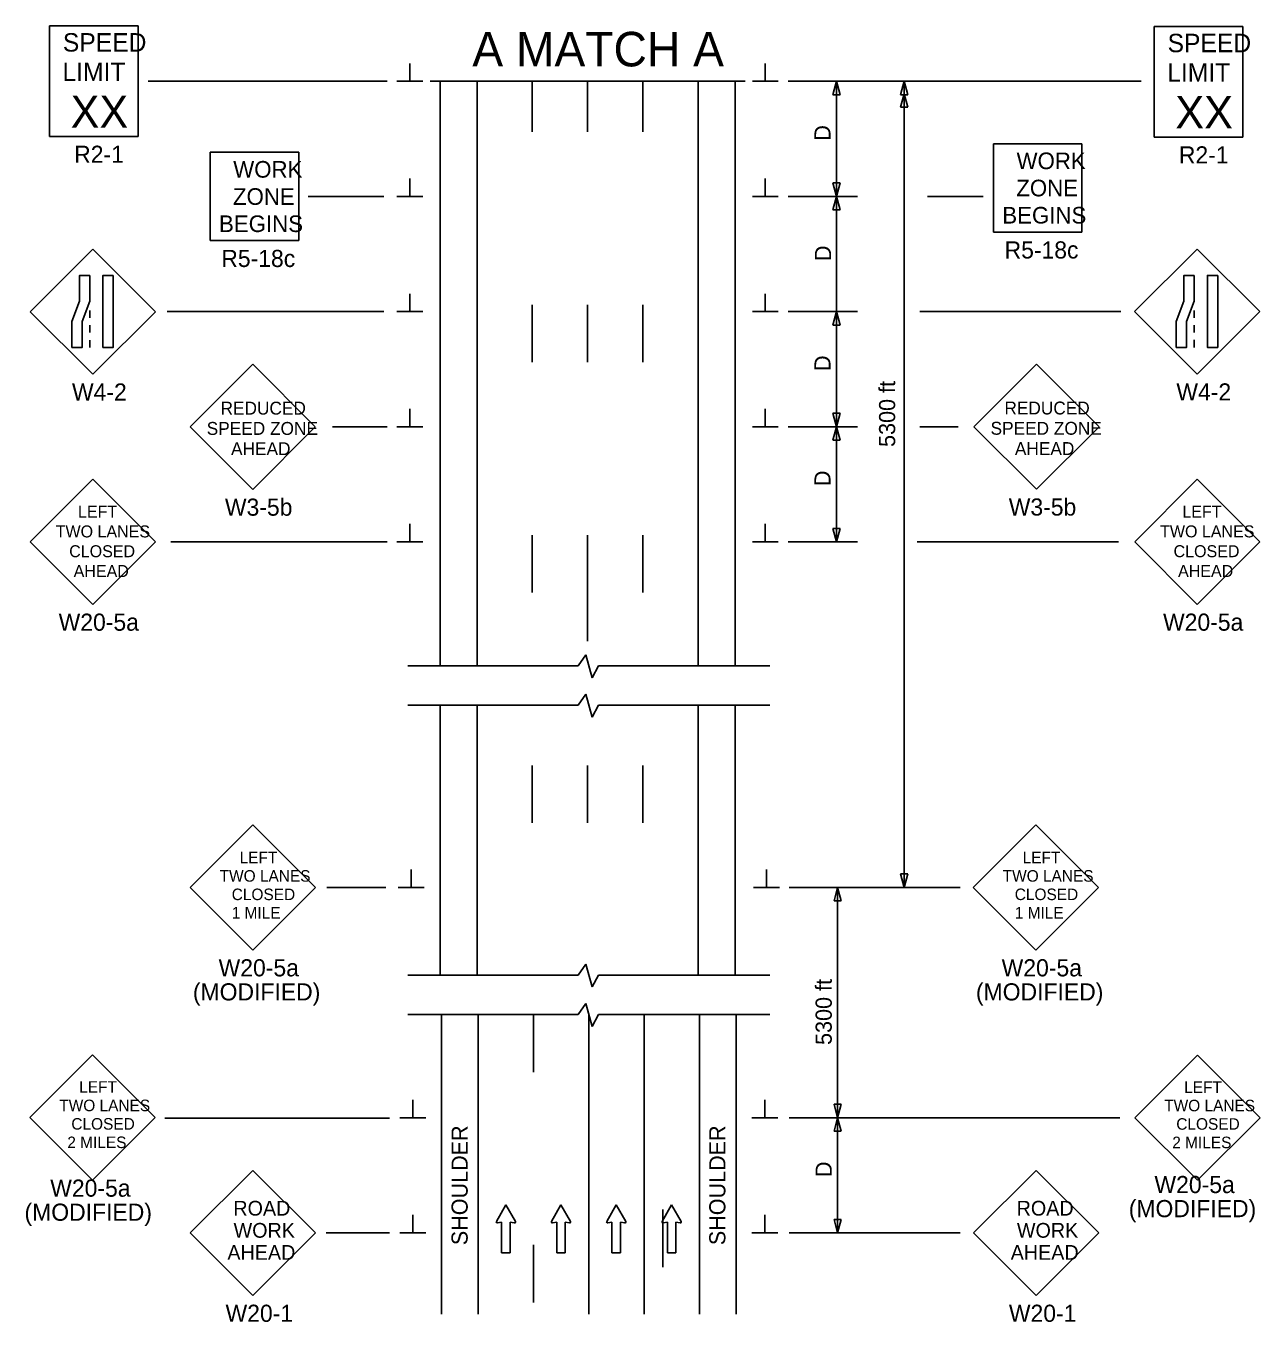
# Model space of a CAD drawing. Extents: x 16486 to 19505, y 5576 to 6998.
# Drawn here: x 17836 to 18371, y 6359 to 6921 of the extents above; entities that cross this region are included whole.
import ezdxf

# ---------------------------------------------------------------- set-up
doc = ezdxf.new("R2010")
doc.units = 0
for name, color, linetype in [('ALI_LEGAL_EX', 7, 'Continuous'), ('MT_SCRATCH_LEVEL_E', 7, 'Continuous'), ('PAVT_EDGE_EX', 7, 'Continuous'), ('TRAFFIC_SIGNS_PR', 7, 'Continuous'), ('TYPICAL_TEXT_DIMEN_PR', 7, 'Continuous')]:
    doc.layers.add(name, color=color, linetype=linetype)

msp = doc.modelspace()

# ---------------------------------------------------------------- linework, layer by layer
at = {"layer": 'ALI_LEGAL_EX'}
for p, q in [((18080.13, 6492.04), (18080.13, 6361.96)), ((18104.13, 6492.04), (18104.13, 6361.96))]:
    msp.add_line(p, q, dxfattribs=at)
for points in [[(18055.61, 6875.22), (18055.61, 6897.24)], [(18079.61, 6875.22), (18079.61, 6897.24)], [(18103.61, 6875.22), (18103.61, 6897.24)], [(18055.61, 6775.22), (18055.61, 6800.22)], [(18079.61, 6775.22), (18079.61, 6800.22)], [(18103.61, 6775.22), (18103.61, 6800.22)], [(18055.61, 6700.22), (18055.61, 6675.22)], [(18079.61, 6700.22), (18079.61, 6675.22)], [(18103.61, 6675.22), (18103.61, 6700.22)], [(18079.61, 6679.08), (18079.61, 6654.08)], [(18055.61, 6600.22), (18055.61, 6575.22)], [(18079.61, 6600.22), (18079.61, 6575.22)], [(18103.61, 6575.22), (18103.61, 6600.22)], [(18056.13, 6492.04), (18056.13, 6467.04)], [(18080.13, 6492.04), (18080.13, 6467.04)], [(18104.13, 6492.04), (18104.13, 6467.04)], [(18112.27, 6407.39), (18112.27, 6382.39)], [(18056.13, 6392.04), (18056.13, 6367.04)], [(18080.13, 6392.04), (18080.13, 6367.04)], [(18104.13, 6392.04), (18104.13, 6367.04)]]:
    msp.add_lwpolyline(points, dxfattribs=at)
at = {"layer": 'MT_SCRATCH_LEVEL_E'}
for p, q in [((18044.13, 6409.47), (18040.02, 6402.23)), ((18048.27, 6402.23), (18044.13, 6409.47)), ((18068.03, 6409.47), (18063.92, 6402.23)), ((18072.18, 6402.23), (18068.03, 6409.47)), ((18092.03, 6409.47), (18087.92, 6402.23)), ((18096.18, 6402.23), (18092.03, 6409.47)), ((18116.08, 6409.47), (18111.97, 6402.23)), ((18120.23, 6402.23), (18116.08, 6409.47)), ((18040.5, 6401.54), (18042.28, 6401.86)), ((18042.28, 6401.86), (18042.28, 6388.6)), ((18046.02, 6388.6), (18046.02, 6401.86)), ((18046.02, 6401.86), (18047.79, 6401.54)), ((18064.4, 6401.54), (18066.18, 6401.86)), ((18066.18, 6401.86), (18066.18, 6388.6)), ((18069.92, 6388.6), (18069.92, 6401.86)), ((18069.92, 6401.86), (18071.7, 6401.54)), ((18088.4, 6401.54), (18090.18, 6401.86)), ((18090.18, 6401.86), (18090.18, 6388.6)), ((18093.92, 6388.6), (18093.92, 6401.86)), ((18093.92, 6401.86), (18095.7, 6401.54)), ((18112.46, 6401.54), (18114.23, 6401.86)), ((18114.23, 6401.86), (18114.23, 6388.6)), ((18117.97, 6388.6), (18117.97, 6401.86)), ((18117.97, 6401.86), (18119.75, 6401.54)), ((18042.28, 6388.6), (18046.02, 6388.6)), ((18066.18, 6388.6), (18069.92, 6388.6)), ((18090.18, 6388.6), (18093.92, 6388.6)), ((18114.23, 6388.6), (18117.97, 6388.6))]:
    msp.add_line(p, q, dxfattribs=at)
for centre, start, end in [((18040.42, 6402), 150.4248, 279.9638), ((18047.86, 6402), 260.0362, 29.7731), ((18064.33, 6402), 150.4248, 279.9638), ((18071.77, 6402), 260.0362, 29.7731), ((18088.33, 6402), 150.4248, 279.9638), ((18095.77, 6402), 260.0362, 29.7731), ((18112.38, 6402), 150.4248, 279.9638), ((18119.82, 6402), 260.0362, 29.7731)]:
    msp.add_arc(centre, 0.463, start, end, dxfattribs=at)
at = {"layer": 'PAVT_EDGE_EX'}
for p, q in [((18015.61, 6897.24), (18015.61, 6643.43)), ((18031.61, 6897.24), (18031.61, 6643.43)), ((18127.61, 6897.24), (18127.61, 6643.43)), ((18143.61, 6897.24), (18143.61, 6643.43)), ((18015.61, 6626.3), (18015.61, 6509.16)), ((18031.61, 6626.3), (18031.61, 6509.16)), ((18127.61, 6626.3), (18127.61, 6509.16)), ((18143.61, 6626.3), (18143.61, 6509.16)), ((18016.13, 6492.02), (18016.13, 6361.96)), ((18032.13, 6492.02), (18032.13, 6361.96)), ((18128.13, 6492.02), (18128.13, 6361.96)), ((18144.13, 6492.02), (18144.13, 6361.96))]:
    msp.add_line(p, q, dxfattribs=at)
at = {"layer": 'TRAFFIC_SIGNS_PR'}
for p, q in [((17846.08, 6921.27), (17884.48, 6921.27)), ((17846.08, 6873.27), (17846.08, 6921.27)), ((17884.48, 6873.27), (17884.48, 6921.27)), ((18325.58, 6921), (18363.98, 6921)), ((18325.58, 6873), (18325.58, 6921)), ((18363.98, 6873), (18363.98, 6921)), ((17846.08, 6873.27), (17884.48, 6873.27)), ((18325.58, 6873), (18363.98, 6873)), ((17915.81, 6828.04), (17915.81, 6866.44)), ((17915.81, 6866.44), (17954.21, 6866.44)), ((17954.21, 6828.04), (17954.21, 6866.44)), ((18255.79, 6831.73), (18255.79, 6870.13)), ((18255.79, 6870.13), (18294.19, 6870.13)), ((18294.19, 6831.73), (18294.19, 6870.13)), ((17915.81, 6828.04), (17954.21, 6828.04)), ((18255.79, 6831.73), (18294.19, 6831.73)), ((17864.85, 6824.36), (17837.7, 6797.2)), ((17892.01, 6797.2), (17864.85, 6824.36)), ((18344.2, 6824.39), (18317.05, 6797.23)), ((18371.35, 6797.23), (18344.2, 6824.39)), ((17837.7, 6797.2), (17864.85, 6770.05)), ((17863.61, 6797.7), (17863.61, 6794.5)), ((17864.85, 6770.05), (17892.01, 6797.2)), ((18317.05, 6797.23), (18344.2, 6770.08)), ((18342.95, 6797.72), (18342.95, 6794.52)), ((18344.2, 6770.08), (18371.35, 6797.23)), ((17863.61, 6791.3), (17863.61, 6788.1)), ((18342.95, 6791.32), (18342.95, 6788.12)), ((17863.61, 6784.9), (17863.61, 6781.7)), ((18342.95, 6784.92), (18342.95, 6781.72)), ((17934.24, 6774.36), (17907.09, 6747.21)), ((17961.39, 6747.21), (17934.24, 6774.36)), ((18274.46, 6774.41), (18247.31, 6747.26)), ((18301.61, 6747.26), (18274.46, 6774.41)), ((17907.09, 6747.21), (17934.24, 6720.05)), ((17934.24, 6720.05), (17961.39, 6747.21)), ((18247.31, 6747.26), (18274.46, 6720.11)), ((18274.46, 6720.11), (18301.61, 6747.26)), ((17864.88, 6724.41), (17837.73, 6697.26)), ((17892.03, 6697.26), (17864.88, 6724.41)), ((18344.23, 6724.43), (18317.07, 6697.28)), ((18371.38, 6697.28), (18344.23, 6724.43)), ((17837.73, 6697.26), (17864.88, 6670.11)), ((17864.88, 6670.11), (17892.03, 6697.26)), ((18317.07, 6697.28), (18344.23, 6670.12)), ((18344.23, 6670.12), (18371.38, 6697.28)), ((17934.32, 6574.42), (17907.13, 6547.24)), ((17961.5, 6547.24), (17934.32, 6574.42)), ((18274.19, 6574.43), (18247.01, 6547.24)), ((18301.38, 6547.24), (18274.19, 6574.43)), ((17907.13, 6547.24), (17934.32, 6520.05)), ((17934.32, 6520.05), (17961.5, 6547.24)), ((18247.01, 6547.24), (18274.19, 6520.05)), ((18274.19, 6520.05), (18301.38, 6547.24)), ((17864.71, 6474.47), (17837.52, 6447.28)), ((17891.89, 6447.28), (17864.71, 6474.47)), ((18344.29, 6474.42), (18317.11, 6447.24)), ((18371.48, 6447.24), (18344.29, 6474.42)), ((17837.52, 6447.28), (17864.71, 6420.1)), ((17864.71, 6420.1), (17891.89, 6447.28)), ((18317.11, 6447.24), (18344.29, 6420.05)), ((18344.29, 6420.05), (18371.48, 6447.24)), ((17934.3, 6424.35), (17907.15, 6397.2)), ((17961.46, 6397.2), (17934.3, 6424.35)), ((18274.29, 6424.35), (18247.14, 6397.2)), ((18301.44, 6397.2), (18274.29, 6424.35)), ((17907.15, 6397.2), (17934.3, 6370.05)), ((17934.3, 6370.05), (17961.46, 6397.2)), ((18247.14, 6397.2), (18274.29, 6370.05)), ((18274.29, 6370.05), (18301.44, 6397.2))]:
    msp.add_line(p, q, dxfattribs=at)
for points in [[(17863.61, 6812.94), (17863.61, 6801.76), (17860.26, 6792.88), (17860.26, 6781.7), (17855.77, 6781.7), (17855.77, 6792.88), (17859.11, 6801.76), (17859.11, 6812.94)], [(17873.74, 6812.94), (17873.74, 6781.7), (17869.25, 6781.7), (17869.25, 6812.94)], [(18342.95, 6812.97), (18342.95, 6801.79), (18339.61, 6792.91), (18339.61, 6781.72), (18335.11, 6781.72), (18335.11, 6792.91), (18338.46, 6801.79), (18338.46, 6812.97)], [(18353.09, 6812.97), (18353.09, 6781.72), (18348.6, 6781.72), (18348.6, 6812.97)]]:
    msp.add_lwpolyline(points, close=True, dxfattribs=at)
at = {"layer": 'TYPICAL_TEXT_DIMEN_PR'}
for p, q in [((18002.48, 6897.24), (18002.48, 6905.02)), ((18156.73, 6897.24), (18156.73, 6905.02)), ((17888.93, 6897.24), (17992.61, 6897.24)), ((17996.86, 6897.24), (18008.11, 6897.24)), ((18011.28, 6897.24), (18147.93, 6897.24)), ((18162.36, 6897.24), (18151.11, 6897.24)), ((18319.82, 6897.24), (18166.61, 6897.24)), ((18186.04, 6891.37), (18187.61, 6897.24)), ((18187.61, 6897.24), (18187.61, 6847.24)), ((18187.61, 6897.24), (18189.18, 6891.37)), ((18215.42, 6891.37), (18216.99, 6897.24)), ((18216.99, 6897.24), (18216.99, 6547.24)), ((18216.99, 6897.24), (18218.56, 6891.37)), ((18187.61, 6891.37), (18186.04, 6891.37)), ((18189.18, 6891.37), (18187.61, 6891.37)), ((18215.42, 6885.96), (18216.99, 6891.82)), ((18216.99, 6891.37), (18215.42, 6891.37)), ((18216.99, 6891.82), (18218.56, 6885.96)), ((18218.56, 6891.37), (18216.99, 6891.37)), ((18216.99, 6885.96), (18215.42, 6885.96)), ((18218.56, 6885.96), (18216.99, 6885.96)), ((18002.48, 6847.24), (18002.48, 6855.02)), ((18156.73, 6847.24), (18156.73, 6855.02)), ((18187.61, 6847.24), (18186.04, 6853.1)), ((18186.04, 6853.1), (18187.61, 6853.1)), ((18187.61, 6853.1), (18189.18, 6853.1)), ((18189.18, 6853.1), (18187.61, 6847.24)), ((17991.11, 6847.24), (17958.38, 6847.24)), ((17996.86, 6847.24), (18008.11, 6847.24)), ((18162.36, 6847.24), (18151.11, 6847.24)), ((18196.69, 6847.24), (18166.61, 6847.24)), ((18186.04, 6841.37), (18187.61, 6847.24)), ((18187.61, 6847.24), (18189.18, 6841.37)), ((18187.61, 6847.24), (18187.61, 6787.24)), ((18251.23, 6847.24), (18227.14, 6847.24)), ((18187.61, 6841.37), (18186.04, 6841.37)), ((18189.18, 6841.37), (18187.61, 6841.37)), ((18002.48, 6797.24), (18002.48, 6805.02)), ((18156.73, 6797.24), (18156.73, 6805.02)), ((17991.11, 6797.24), (17897.08, 6797.24)), ((17996.86, 6797.24), (18008.11, 6797.24)), ((18162.36, 6797.24), (18151.11, 6797.24)), ((18196.69, 6797.24), (18166.61, 6797.24)), ((18186.04, 6791.37), (18187.61, 6797.24)), ((18187.61, 6797.24), (18187.61, 6747.24)), ((18187.61, 6797.24), (18189.18, 6791.37)), ((18311.11, 6797.24), (18223.75, 6797.24)), ((18187.61, 6791.37), (18186.04, 6791.37)), ((18189.18, 6791.37), (18187.61, 6791.37)), ((18002.48, 6747.24), (18002.48, 6755.02)), ((18156.73, 6747.24), (18156.73, 6755.02)), ((18187.61, 6747.24), (18186.04, 6753.1)), ((18186.04, 6753.1), (18187.61, 6753.1)), ((18187.61, 6753.1), (18189.18, 6753.1)), ((18189.18, 6753.1), (18187.61, 6747.24)), ((17968.9, 6747.24), (17992.61, 6747.24)), ((17996.86, 6747.24), (18008.11, 6747.24)), ((18162.36, 6747.24), (18151.11, 6747.24)), ((18196.69, 6747.24), (18166.61, 6747.24)), ((18186.04, 6741.37), (18187.61, 6747.24)), ((18187.61, 6747.24), (18187.61, 6697.24)), ((18187.61, 6747.24), (18189.18, 6741.37)), ((18240.44, 6747.24), (18223.75, 6747.24)), ((18187.61, 6741.37), (18186.04, 6741.37)), ((18189.18, 6741.37), (18187.61, 6741.37)), ((18002.48, 6697.24), (18002.48, 6705.02)), ((18156.73, 6697.24), (18156.73, 6705.02)), ((18187.61, 6697.24), (18186.04, 6703.1)), ((18186.04, 6703.1), (18187.61, 6703.1)), ((18187.61, 6703.1), (18189.18, 6703.1)), ((18189.18, 6703.1), (18187.61, 6697.24)), ((17898.77, 6697.24), (17992.61, 6697.24)), ((17996.86, 6697.24), (18008.11, 6697.24)), ((18162.36, 6697.24), (18151.11, 6697.24)), ((18196.69, 6697.24), (18166.61, 6697.24)), ((18310.07, 6697.24), (18222.62, 6697.24)), ((18078.8, 6648.23), (18075.54, 6643.43)), ((18081.54, 6638.29), (18078.8, 6648.23)), ((18075.54, 6643.43), (18001.63, 6643.43)), ((18084.28, 6643.43), (18081.54, 6638.29)), ((18158.63, 6643.43), (18084.28, 6643.43)), ((18078.8, 6631.1), (18075.54, 6626.3)), ((18081.54, 6621.16), (18078.8, 6631.1)), ((18075.54, 6626.3), (18001.63, 6626.3)), ((18084.28, 6626.3), (18081.54, 6621.16)), ((18158.63, 6626.3), (18084.28, 6626.3)), ((18003, 6547.24), (18003, 6555.02)), ((18157.25, 6547.24), (18157.25, 6555.02)), ((18216.99, 6547.24), (18215.42, 6553.1)), ((18215.42, 6553.1), (18216.99, 6553.1)), ((18216.99, 6553.1), (18218.56, 6553.1)), ((18218.56, 6553.1), (18216.99, 6547.24)), ((17966.45, 6547.24), (17992.08, 6547.24)), ((17997.38, 6547.24), (18008.63, 6547.24)), ((18162.88, 6547.24), (18151.63, 6547.24)), ((18241.31, 6547.24), (18167.13, 6547.24)), ((18186.56, 6541.37), (18188.13, 6547.24)), ((18188.13, 6547.24), (18188.13, 6447.24)), ((18188.13, 6547.24), (18189.7, 6541.37)), ((18188.13, 6541.37), (18186.56, 6541.37)), ((18189.7, 6541.37), (18188.13, 6541.37)), ((18078.8, 6513.96), (18075.54, 6509.16)), ((18081.54, 6504.02), (18078.8, 6513.96)), ((18075.54, 6509.16), (18001.63, 6509.16)), ((18084.28, 6509.16), (18081.54, 6504.02)), ((18158.63, 6509.16), (18084.28, 6509.16)), ((18078.8, 6496.82), (18075.54, 6492.02)), ((18081.54, 6486.88), (18078.8, 6496.82)), ((18075.54, 6492.02), (18001.63, 6492.02)), ((18084.28, 6492.02), (18081.54, 6486.88)), ((18158.63, 6492.02), (18084.28, 6492.02)), ((18003.75, 6447.24), (18003.75, 6455.02)), ((18156.5, 6447.24), (18156.5, 6455.02)), ((18188.13, 6447.24), (18186.56, 6453.1)), ((18186.56, 6453.1), (18188.13, 6453.1)), ((18188.13, 6453.1), (18189.7, 6453.1)), ((18189.7, 6453.1), (18188.13, 6447.24)), ((17896.12, 6447.08), (17993.62, 6447.08)), ((17998.13, 6447.24), (18009.38, 6447.24)), ((18162.13, 6447.24), (18150.88, 6447.24)), ((18310.6, 6447.24), (18167.13, 6447.24)), ((18186.56, 6441.37), (18188.13, 6447.24)), ((18188.13, 6447.24), (18188.13, 6397.24)), ((18188.13, 6447.24), (18189.7, 6441.37)), ((18188.13, 6441.37), (18186.56, 6441.37)), ((18189.7, 6441.37), (18188.13, 6441.37)), ((18003.75, 6397.24), (18003.75, 6405.02)), ((18156.5, 6397.24), (18156.5, 6405.02)), ((18188.13, 6397.24), (18186.56, 6403.1)), ((18186.56, 6403.1), (18188.13, 6403.1)), ((18188.13, 6403.1), (18189.7, 6403.1)), ((18189.7, 6403.1), (18188.13, 6397.24)), ((17966.11, 6397.24), (17993.62, 6397.24)), ((17998.13, 6397.24), (18009.38, 6397.24)), ((18162.13, 6397.24), (18150.88, 6397.24)), ((18241.31, 6397.24), (18167.13, 6397.24))]:
    msp.add_line(p, q, dxfattribs=at)

# ---------------------------------------------------------------- texts
at = {"layer": 'TRAFFIC_SIGNS_PR'}
for s, height, p in [('SPEED', 8, (17851.85, 6910.13)), ('SPEED', 8, (18331.34, 6909.86)), ('LIMIT', 8, (17851.69, 6897.33)), ('LIMIT', 8, (18331.18, 6897.06)), ('XX', 14.031, (17855.2, 6877.03)), ('XX', 14.031, (18334.69, 6876.76)), ('R2-1', 7.44, (17856.76, 6861.83)), ('WORK', 7.217, (18265.79, 6859.09)), ('R2-1', 7.44, (18336.25, 6861.56)), ('WORK', 7.217, (17925.8, 6855.4)), ('ZONE', 7.217, (18265.67, 6847.28)), ('ZONE', 7.217, (17925.69, 6843.59)), ('BEGINS', 7.217, (17919.62, 6831.78)), ('BEGINS', 7.217, (18259.6, 6835.47)), ('R5-18c', 7.44, (18260.6, 6820.29)), ('R5-18c', 7.44, (17920.62, 6816.6)), ('W4-2', 7.44, (17855.81, 6758.61)), ('W4-2', 7.44, (18335.16, 6758.64)), ('REDUCED', 5.6, (17920.3, 6752.51)), ('REDUCED', 5.6, (18260.52, 6752.57)), ('SPEED ZONE', 5.6, (17914.29, 6743.71)), ('SPEED ZONE', 5.6, (18254.51, 6743.77)), ('AHEAD', 5.6, (17924.85, 6734.91)), ('AHEAD', 5.6, (18265.07, 6734.97)), ('W3-5b', 7.44, (17922.19, 6708.61)), ('W3-5b', 7.44, (18262.41, 6708.67)), ('LEFT', 5.2, (17858.42, 6707.79)), ('LEFT', 5.2, (18337.76, 6707.81)), ('TWO LANES', 5.2, (17848.74, 6699.19)), ('TWO LANES', 5.2, (18328.09, 6699.21)), ('CLOSED', 5.2, (17854.6, 6690.59)), ('CLOSED', 5.2, (18333.94, 6690.61)), ('AHEAD', 5.2, (17856.54, 6681.99)), ('AHEAD', 5.2, (18335.89, 6682.01)), ('W20-5a', 7.44, (17850.02, 6658.67)), ('W20-5a', 7.44, (18329.37, 6658.68)), ('LEFT', 5.006, (17928.56, 6557.73)), ('LEFT', 5.006, (18268.43, 6557.73)), ('TWO LANES', 5.006, (17919.91, 6549.72)), ('TWO LANES', 5.006, (18259.78, 6549.72)), ('CLOSED', 5.006, (17925.14, 6541.71)), ('CLOSED', 5.006, (18265.01, 6541.72)), ('1 MILE', 5.006, (17925.13, 6533.71)), ('1 MILE', 5.006, (18265.01, 6533.71)), ('W20-5a', 7.449, (17919.44, 6508.6)), ('W20-5a', 7.449, (18259.31, 6508.6)), ('(MODIFIED)', 7.449, (17908.28, 6498.15)), ('(MODIFIED)', 7.449, (18248.15, 6498.15)), ('LEFT', 5.006, (17858.95, 6458.08)), ('LEFT', 5.006, (18338.54, 6458.03)), ('TWO LANES', 5.006, (17850.3, 6450.07)), ('TWO LANES', 5.006, (18329.88, 6450.02)), ('CLOSED', 5.006, (17855.53, 6442.06)), ('CLOSED', 5.006, (18335.12, 6442.02)), ('2 MILES', 5.006, (17853.78, 6434.05)), ('2 MILES', 5.006, (18333.37, 6434.01)), ('W20-5a', 7.449, (18325.64, 6414.5)), ('W20-5a', 7.449, (17846.36, 6412.94)), ('(MODIFIED)', 7.449, (17835.2, 6402.49)), ('ROAD', 6.4, (17925.85, 6404.74)), ('ROAD', 6.4, (18265.83, 6404.74)), ('(MODIFIED)', 7.449, (18314.48, 6404.05)), ('WORK', 6.4, (17925.95, 6395.14)), ('WORK', 6.4, (18265.94, 6395.14)), ('AHEAD', 6.4, (17923.26, 6385.54)), ('AHEAD', 6.4, (18263.25, 6385.54)), ('W20-1', 7.44, (17922.47, 6358.61)), ('W20-1', 7.44, (18262.46, 6358.61))]:
    msp.add_text(s, height=height, dxfattribs=at).set_placement(p)
at = {"layer": 'TYPICAL_TEXT_DIMEN_PR'}
msp.add_text('A MATCH A', height=15, dxfattribs=at).set_placement((18029.57, 6903.7))
for s, p in [('D', (18185.05, 6871.45)), ('D', (18185.26, 6819.17)), ('D', (18185.05, 6771.45)), ('5300 ft', (18213.1, 6738.48)), ('D', (18185.05, 6721.45)), ('5300 ft', (18185.57, 6478.84)), ('SHOULDER', (18027.55, 6391.89)), ('SHOULDER', (18139.41, 6391.89)), ('D', (18185.57, 6421.46))]:
    msp.add_text(s, height=7, rotation=90, dxfattribs=at).set_placement(p)

doc.saveas('drawing.dxf')
